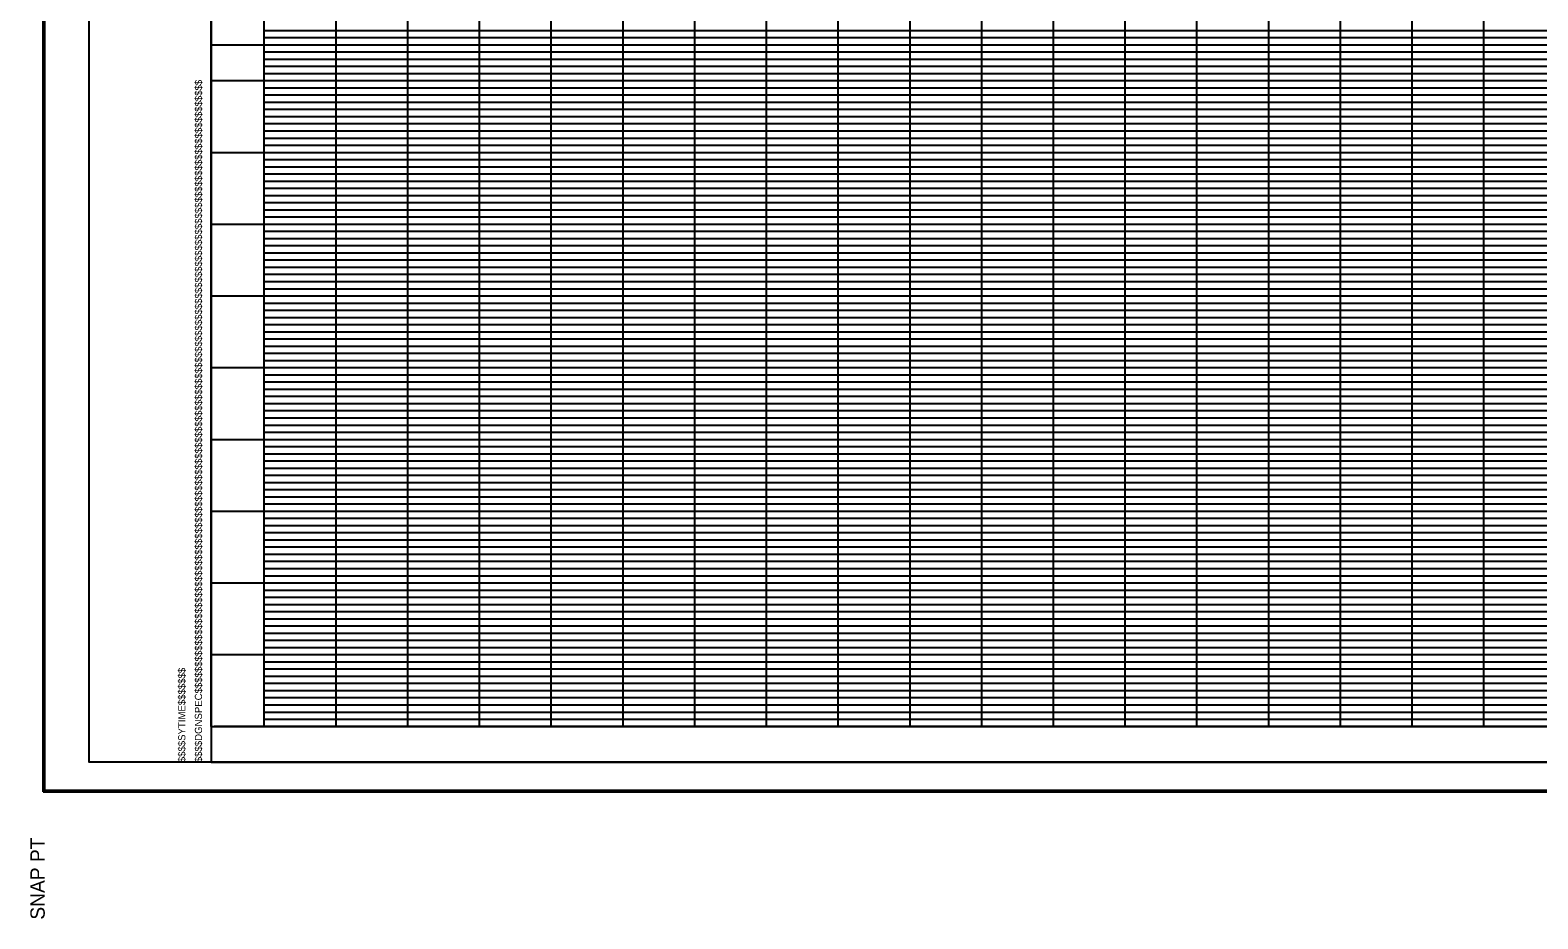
# Model space of a CAD drawing. Extents: x -200 to 1681865, y -325 to 520634.
# Drawn here: x 1680154 to 1681205, y 519391 to 520010 of the extents above; entities that cross this region are included whole.
import ezdxf

# ---------------------------------------------------------------- set-up
doc = ezdxf.new("R2010")
doc.units = 0
for name, color, linetype in [('DESIGN - PROFILE - Proposed Text', 7, 'Continuous'), ('DESIGN - SHEET - Corner Text', 7, 'Continuous'), ('DESIGN - SHEET - Light Grid', 7, 'Continuous'), ('DESIGN - SHEET - Linework', 7, 'Continuous'), ('DESIGN - SHEET - Plot Shape', 7, 'Continuous')]:
    doc.layers.add(name, color=color, linetype=linetype)

msp = doc.modelspace()

# ---------------------------------------------------------------- linework, layer by layer
at = {"layer": 'DESIGN - PROFILE - Proposed Text'}
msp.add_line((1680280, 519499.8), (1680280, 519499.8), dxfattribs=at)
at = {"layer": 'DESIGN - SHEET - Corner Text'}
msp.add_line((1680280, 519999.8), (1681654.2, 519999.8), dxfattribs=at)
at = {"layer": 'DESIGN - SHEET - Light Grid'}
for p, q in [((1680317.1, 520009.8), (1680617.1, 520009.8)), ((1680317.1, 520004.8), (1680617.1, 520004.8)), ((1680617.1, 520009.8), (1680967.1, 520009.8)), ((1680617.1, 520004.8), (1680967.1, 520004.8)), ((1680967.1, 520009.8), (1681317.1, 520009.8)), ((1680967.1, 520004.8), (1681317.1, 520004.8)), ((1680317.1, 519999.8), (1680617.1, 519999.8)), ((1680317.1, 519994.8), (1680617.1, 519994.8)), ((1680617.1, 519999.8), (1680967.1, 519999.8)), ((1680617.1, 519994.8), (1680967.1, 519994.8)), ((1680967.1, 519999.8), (1681317.1, 519999.8)), ((1680967.1, 519994.8), (1681317.1, 519994.8)), ((1680317.1, 519989.8), (1680617.1, 519989.8)), ((1680317.1, 519984.8), (1680617.1, 519984.8)), ((1680617.1, 519989.8), (1680967.1, 519989.8)), ((1680617.1, 519984.8), (1680967.1, 519984.8)), ((1680967.1, 519989.8), (1681317.1, 519989.8)), ((1680967.1, 519984.8), (1681317.1, 519984.8)), ((1680317.1, 519979.8), (1680617.1, 519979.8)), ((1680617.1, 519979.8), (1680967.1, 519979.8)), ((1680967.1, 519979.8), (1681317.1, 519979.8)), ((1680317.1, 519969.8), (1680617.1, 519969.8)), ((1680317.1, 519964.8), (1680617.1, 519964.8)), ((1680317.1, 519959.8), (1680617.1, 519959.8)), ((1680617.1, 519969.8), (1680967.1, 519969.8)), ((1680617.1, 519964.8), (1680967.1, 519964.8)), ((1680617.1, 519959.8), (1680967.1, 519959.8)), ((1680967.1, 519969.8), (1681317.1, 519969.8)), ((1680967.1, 519964.8), (1681317.1, 519964.8)), ((1680967.1, 519959.8), (1681317.1, 519959.8)), ((1680317.1, 519954.8), (1680617.1, 519954.8)), ((1680317.1, 519949.8), (1680617.1, 519949.8)), ((1680617.1, 519954.8), (1680967.1, 519954.8)), ((1680617.1, 519949.8), (1680967.1, 519949.8)), ((1680967.1, 519954.8), (1681317.1, 519954.8)), ((1680967.1, 519949.8), (1681317.1, 519949.8)), ((1680317.1, 519944.8), (1680617.1, 519944.8)), ((1680317.1, 519939.8), (1680617.1, 519939.8)), ((1680617.1, 519944.8), (1680967.1, 519944.8)), ((1680617.1, 519939.8), (1680967.1, 519939.8)), ((1680967.1, 519944.8), (1681317.1, 519944.8)), ((1680967.1, 519939.8), (1681317.1, 519939.8)), ((1680317.1, 519934.8), (1680617.1, 519934.8)), ((1680317.1, 519929.8), (1680617.1, 519929.8)), ((1680617.1, 519934.8), (1680967.1, 519934.8)), ((1680617.1, 519929.8), (1680967.1, 519929.8)), ((1680967.1, 519934.8), (1681317.1, 519934.8)), ((1680967.1, 519929.8), (1681317.1, 519929.8)), ((1680317.1, 519919.8), (1680617.1, 519919.8)), ((1680617.1, 519919.8), (1680967.1, 519919.8)), ((1680967.1, 519919.8), (1681317.1, 519919.8)), ((1680317.1, 519914.8), (1680617.1, 519914.8)), ((1680317.1, 519909.8), (1680617.1, 519909.8)), ((1680617.1, 519914.8), (1680967.1, 519914.8)), ((1680617.1, 519909.8), (1680967.1, 519909.8)), ((1680967.1, 519914.8), (1681317.1, 519914.8)), ((1680967.1, 519909.8), (1681317.1, 519909.8)), ((1680317.1, 519904.8), (1680617.1, 519904.8)), ((1680317.1, 519899.8), (1680617.1, 519899.8)), ((1680617.1, 519904.8), (1680967.1, 519904.8)), ((1680617.1, 519899.8), (1680967.1, 519899.8)), ((1680967.1, 519904.8), (1681317.1, 519904.8)), ((1680967.1, 519899.8), (1681317.1, 519899.8)), ((1680317.1, 519894.8), (1680617.1, 519894.8)), ((1680317.1, 519889.8), (1680617.1, 519889.8)), ((1680617.1, 519894.8), (1680967.1, 519894.8)), ((1680617.1, 519889.8), (1680967.1, 519889.8)), ((1680967.1, 519894.8), (1681317.1, 519894.8)), ((1680967.1, 519889.8), (1681317.1, 519889.8)), ((1680317.1, 519884.8), (1680617.1, 519884.8)), ((1680317.1, 519879.8), (1680617.1, 519879.8)), ((1680617.1, 519884.8), (1680967.1, 519884.8)), ((1680617.1, 519879.8), (1680967.1, 519879.8)), ((1680967.1, 519884.8), (1681317.1, 519884.8)), ((1680967.1, 519879.8), (1681317.1, 519879.8)), ((1680317.1, 519869.8), (1680617.1, 519869.8)), ((1680617.1, 519869.8), (1680967.1, 519869.8)), ((1680967.1, 519869.8), (1681317.1, 519869.8)), ((1680317.1, 519864.8), (1680617.1, 519864.8)), ((1680317.1, 519859.8), (1680617.1, 519859.8)), ((1680317.1, 519854.8), (1680617.1, 519854.8)), ((1680617.1, 519864.8), (1680967.1, 519864.8)), ((1680617.1, 519859.8), (1680967.1, 519859.8)), ((1680617.1, 519854.8), (1680967.1, 519854.8)), ((1680967.1, 519864.8), (1681317.1, 519864.8)), ((1680967.1, 519859.8), (1681317.1, 519859.8)), ((1680967.1, 519854.8), (1681317.1, 519854.8)), ((1680317.1, 519849.8), (1680617.1, 519849.8)), ((1680317.1, 519844.8), (1680617.1, 519844.8)), ((1680617.1, 519849.8), (1680967.1, 519849.8)), ((1680617.1, 519844.8), (1680967.1, 519844.8)), ((1680967.1, 519849.8), (1681317.1, 519849.8)), ((1680967.1, 519844.8), (1681317.1, 519844.8)), ((1680317.1, 519839.8), (1680617.1, 519839.8)), ((1680317.1, 519834.8), (1680617.1, 519834.8)), ((1680617.1, 519839.8), (1680967.1, 519839.8)), ((1680617.1, 519834.8), (1680967.1, 519834.8)), ((1680967.1, 519839.8), (1681317.1, 519839.8)), ((1680967.1, 519834.8), (1681317.1, 519834.8)), ((1680317.1, 519829.8), (1680617.1, 519829.8)), ((1680617.1, 519829.8), (1680967.1, 519829.8)), ((1680967.1, 519829.8), (1681317.1, 519829.8)), ((1680317.1, 519819.8), (1680617.1, 519819.8)), ((1680317.1, 519814.8), (1680617.1, 519814.8)), ((1680617.1, 519819.8), (1680967.1, 519819.8)), ((1680617.1, 519814.8), (1680967.1, 519814.8)), ((1680967.1, 519819.8), (1681317.1, 519819.8)), ((1680967.1, 519814.8), (1681317.1, 519814.8)), ((1680317.1, 519809.8), (1680617.1, 519809.8)), ((1680317.1, 519804.8), (1680617.1, 519804.8)), ((1680617.1, 519809.8), (1680967.1, 519809.8)), ((1680617.1, 519804.8), (1680967.1, 519804.8)), ((1680967.1, 519809.8), (1681317.1, 519809.8)), ((1680967.1, 519804.8), (1681317.1, 519804.8)), ((1680317.1, 519799.8), (1680617.1, 519799.8)), ((1680317.1, 519794.8), (1680617.1, 519794.8)), ((1680617.1, 519799.8), (1680967.1, 519799.8)), ((1680617.1, 519794.8), (1680967.1, 519794.8)), ((1680967.1, 519799.8), (1681317.1, 519799.8)), ((1680967.1, 519794.8), (1681317.1, 519794.8)), ((1680317.1, 519789.8), (1680617.1, 519789.8)), ((1680317.1, 519784.8), (1680617.1, 519784.8)), ((1680617.1, 519789.8), (1680967.1, 519789.8)), ((1680617.1, 519784.8), (1680967.1, 519784.8)), ((1680967.1, 519789.8), (1681317.1, 519789.8)), ((1680967.1, 519784.8), (1681317.1, 519784.8)), ((1680317.1, 519779.8), (1680617.1, 519779.8)), ((1680617.1, 519779.8), (1680967.1, 519779.8)), ((1680967.1, 519779.8), (1681317.1, 519779.8)), ((1680317.1, 519769.8), (1680617.1, 519769.8)), ((1680317.1, 519764.8), (1680617.1, 519764.8)), ((1680317.1, 519759.8), (1680617.1, 519759.8)), ((1680617.1, 519769.8), (1680967.1, 519769.8)), ((1680617.1, 519764.8), (1680967.1, 519764.8)), ((1680617.1, 519759.8), (1680967.1, 519759.8)), ((1680967.1, 519769.8), (1681317.1, 519769.8)), ((1680967.1, 519764.8), (1681317.1, 519764.8)), ((1680967.1, 519759.8), (1681317.1, 519759.8)), ((1680317.1, 519754.8), (1680617.1, 519754.8)), ((1680317.1, 519749.8), (1680617.1, 519749.8)), ((1680617.1, 519754.8), (1680967.1, 519754.8)), ((1680617.1, 519749.8), (1680967.1, 519749.8)), ((1680967.1, 519754.8), (1681317.1, 519754.8)), ((1680967.1, 519749.8), (1681317.1, 519749.8)), ((1680317.1, 519744.8), (1680617.1, 519744.8)), ((1680317.1, 519739.8), (1680617.1, 519739.8)), ((1680617.1, 519744.8), (1680967.1, 519744.8)), ((1680617.1, 519739.8), (1680967.1, 519739.8)), ((1680967.1, 519744.8), (1681317.1, 519744.8)), ((1680967.1, 519739.8), (1681317.1, 519739.8)), ((1680317.1, 519734.8), (1680617.1, 519734.8)), ((1680317.1, 519729.8), (1680617.1, 519729.8)), ((1680617.1, 519734.8), (1680967.1, 519734.8)), ((1680617.1, 519729.8), (1680967.1, 519729.8)), ((1680967.1, 519734.8), (1681317.1, 519734.8)), ((1680967.1, 519729.8), (1681317.1, 519729.8)), ((1680317.1, 519719.8), (1680617.1, 519719.8)), ((1680617.1, 519719.8), (1680967.1, 519719.8)), ((1680967.1, 519719.8), (1681317.1, 519719.8)), ((1680317.1, 519714.8), (1680617.1, 519714.8)), ((1680317.1, 519709.8), (1680617.1, 519709.8)), ((1680617.1, 519714.8), (1680967.1, 519714.8)), ((1680617.1, 519709.8), (1680967.1, 519709.8)), ((1680967.1, 519714.8), (1681317.1, 519714.8)), ((1680967.1, 519709.8), (1681317.1, 519709.8)), ((1680317.1, 519704.8), (1680617.1, 519704.8)), ((1680317.1, 519699.8), (1680617.1, 519699.8)), ((1680617.1, 519704.8), (1680967.1, 519704.8)), ((1680617.1, 519699.8), (1680967.1, 519699.8)), ((1680967.1, 519704.8), (1681317.1, 519704.8)), ((1680967.1, 519699.8), (1681317.1, 519699.8)), ((1680317.1, 519694.8), (1680617.1, 519694.8)), ((1680317.1, 519689.8), (1680617.1, 519689.8)), ((1680617.1, 519694.8), (1680967.1, 519694.8)), ((1680617.1, 519689.8), (1680967.1, 519689.8)), ((1680967.1, 519694.8), (1681317.1, 519694.8)), ((1680967.1, 519689.8), (1681317.1, 519689.8)), ((1680317.1, 519684.8), (1680617.1, 519684.8)), ((1680317.1, 519679.8), (1680617.1, 519679.8)), ((1680617.1, 519684.8), (1680967.1, 519684.8)), ((1680617.1, 519679.8), (1680967.1, 519679.8)), ((1680967.1, 519684.8), (1681317.1, 519684.8)), ((1680967.1, 519679.8), (1681317.1, 519679.8)), ((1680317.1, 519669.8), (1680617.1, 519669.8)), ((1680617.1, 519669.8), (1680967.1, 519669.8)), ((1680967.1, 519669.8), (1681317.1, 519669.8)), ((1680317.1, 519664.8), (1680617.1, 519664.8)), ((1680317.1, 519659.8), (1680617.1, 519659.8)), ((1680317.1, 519654.8), (1680617.1, 519654.8)), ((1680617.1, 519664.8), (1680967.1, 519664.8)), ((1680617.1, 519659.8), (1680967.1, 519659.8)), ((1680617.1, 519654.8), (1680967.1, 519654.8)), ((1680967.1, 519664.8), (1681317.1, 519664.8)), ((1680967.1, 519659.8), (1681317.1, 519659.8)), ((1680967.1, 519654.8), (1681317.1, 519654.8)), ((1680317.1, 519649.8), (1680617.1, 519649.8)), ((1680317.1, 519644.8), (1680617.1, 519644.8)), ((1680617.1, 519649.8), (1680967.1, 519649.8)), ((1680617.1, 519644.8), (1680967.1, 519644.8)), ((1680967.1, 519649.8), (1681317.1, 519649.8)), ((1680967.1, 519644.8), (1681317.1, 519644.8)), ((1680317.1, 519639.8), (1680617.1, 519639.8)), ((1680317.1, 519634.8), (1680617.1, 519634.8)), ((1680617.1, 519639.8), (1680967.1, 519639.8)), ((1680617.1, 519634.8), (1680967.1, 519634.8)), ((1680967.1, 519639.8), (1681317.1, 519639.8)), ((1680967.1, 519634.8), (1681317.1, 519634.8)), ((1680317.1, 519629.8), (1680617.1, 519629.8)), ((1680617.1, 519629.8), (1680967.1, 519629.8)), ((1680967.1, 519629.8), (1681317.1, 519629.8)), ((1680317.1, 519619.8), (1680617.1, 519619.8)), ((1680317.1, 519614.8), (1680617.1, 519614.8)), ((1680617.1, 519619.8), (1680967.1, 519619.8)), ((1680617.1, 519614.8), (1680967.1, 519614.8)), ((1680967.1, 519619.8), (1681317.1, 519619.8)), ((1680967.1, 519614.8), (1681317.1, 519614.8)), ((1680317.1, 519609.8), (1680617.1, 519609.8)), ((1680317.1, 519604.8), (1680617.1, 519604.8)), ((1680617.1, 519609.8), (1680967.1, 519609.8)), ((1680617.1, 519604.8), (1680967.1, 519604.8)), ((1680967.1, 519609.8), (1681317.1, 519609.8)), ((1680967.1, 519604.8), (1681317.1, 519604.8)), ((1680317.1, 519599.8), (1680617.1, 519599.8)), ((1680317.1, 519594.8), (1680617.1, 519594.8)), ((1680617.1, 519599.8), (1680967.1, 519599.8)), ((1680617.1, 519594.8), (1680967.1, 519594.8)), ((1680967.1, 519599.8), (1681317.1, 519599.8)), ((1680967.1, 519594.8), (1681317.1, 519594.8)), ((1680317.1, 519589.8), (1680617.1, 519589.8)), ((1680317.1, 519584.8), (1680617.1, 519584.8)), ((1680617.1, 519589.8), (1680967.1, 519589.8)), ((1680617.1, 519584.8), (1680967.1, 519584.8)), ((1680967.1, 519589.8), (1681317.1, 519589.8)), ((1680967.1, 519584.8), (1681317.1, 519584.8)), ((1680317.1, 519579.8), (1680617.1, 519579.8)), ((1680617.1, 519579.8), (1680967.1, 519579.8)), ((1680967.1, 519579.8), (1681317.1, 519579.8)), ((1680317.1, 519569.8), (1680617.1, 519569.8)), ((1680317.1, 519564.8), (1680617.1, 519564.8)), ((1680617.1, 519569.8), (1680967.1, 519569.8)), ((1680617.1, 519564.8), (1680967.1, 519564.8)), ((1680967.1, 519569.8), (1681317.1, 519569.8)), ((1680967.1, 519564.8), (1681317.1, 519564.8)), ((1680317.1, 519559.8), (1680617.1, 519559.8)), ((1680317.1, 519554.8), (1680617.1, 519554.8)), ((1680317.1, 519549.8), (1680617.1, 519549.8)), ((1680617.1, 519559.8), (1680967.1, 519559.8)), ((1680617.1, 519554.8), (1680967.1, 519554.8)), ((1680617.1, 519549.8), (1680967.1, 519549.8)), ((1680967.1, 519559.8), (1681317.1, 519559.8)), ((1680967.1, 519554.8), (1681317.1, 519554.8)), ((1680967.1, 519549.8), (1681317.1, 519549.8)), ((1680317.1, 519544.8), (1680617.1, 519544.8)), ((1680317.1, 519539.8), (1680617.1, 519539.8)), ((1680617.1, 519544.8), (1680967.1, 519544.8)), ((1680617.1, 519539.8), (1680967.1, 519539.8)), ((1680967.1, 519544.8), (1681317.1, 519544.8)), ((1680967.1, 519539.8), (1681317.1, 519539.8)), ((1680317.1, 519534.8), (1680617.1, 519534.8)), ((1680317.1, 519529.8), (1680617.1, 519529.8)), ((1680617.1, 519534.8), (1680967.1, 519534.8)), ((1680617.1, 519529.8), (1680967.1, 519529.8)), ((1680967.1, 519534.8), (1681317.1, 519534.8)), ((1680967.1, 519529.8), (1681317.1, 519529.8))]:
    msp.add_line(p, q, dxfattribs=at)
at = {"layer": 'DESIGN - SHEET - Linework'}
for p, q in [((1680163.1, 519479.1), (1680163.1, 520570.5)), ((1680317.1, 519524.8), (1680317.1, 520524.8)), ((1680367.1, 519524.8), (1680367.1, 520524.8)), ((1680417.1, 519524.8), (1680417.1, 520524.8)), ((1680467.1, 519524.8), (1680467.1, 520524.8)), ((1680517.1, 519524.8), (1680517.1, 520524.8)), ((1680567.1, 519524.8), (1680567.1, 520524.8)), ((1680617.1, 519524.8), (1680617.1, 520524.8)), ((1680667.1, 519524.8), (1680667.1, 520524.8)), ((1680717.1, 519524.8), (1680717.1, 520524.8)), ((1680767.1, 519524.8), (1680767.1, 520524.8)), ((1680817.1, 519524.8), (1680817.1, 520524.8)), ((1680867.1, 519524.8), (1680867.1, 520524.8)), ((1680917.1, 519524.8), (1680917.1, 520524.8)), ((1680967.1, 519524.8), (1680967.1, 520524.8)), ((1681017.1, 519524.8), (1681017.1, 520524.8)), ((1681067.1, 519524.8), (1681067.1, 520524.8)), ((1681117.1, 519524.8), (1681117.1, 520524.8)), ((1681167.1, 519524.8), (1681167.1, 520524.8)), ((1680280, 519974.8), (1681654.2, 519974.8)), ((1680280, 519924.8), (1681654.2, 519924.8)), ((1680280, 519874.8), (1681654.2, 519874.8)), ((1680280, 519824.8), (1681654.2, 519824.8)), ((1680280, 519774.8), (1681654.2, 519774.8)), ((1680280, 519724.8), (1681654.2, 519724.8)), ((1680280, 519674.8), (1681654.2, 519674.8)), ((1680280, 519624.8), (1681654.2, 519624.8)), ((1680280, 519574.8), (1681654.2, 519574.8)), ((1680280, 519524.8), (1681654.2, 519524.8)), ((1680163.1, 519479.1), (1681865.1, 519479.1))]:
    msp.add_line(p, q, dxfattribs=at)
for points in [[(1680280, 520549.8), (1680280, 519499.8), (1681854.2, 519499.8), (1681854.2, 520549.8), (1680280, 520549.8)], [(1680280, 519524.8), (1680280, 520524.8), (1681654.2, 520524.8), (1681654.2, 519524.8), (1680282.1, 519524.8)]]:
    msp.add_lwpolyline(points, dxfattribs=at)
at = {"layer": 'DESIGN - SHEET - Plot Shape'}
for points in [[(1680164.1, 520569.5), (1681864.1, 520569.5), (1681864.1, 519480.1), (1680164.1, 519480.1)], [(1680195, 520549.8), (1681854.2, 520549.8), (1681854.2, 519499.8), (1680195, 519499.8)]]:
    msp.add_lwpolyline(points, close=True, dxfattribs=at)

# ---------------------------------------------------------------- texts
at = {"layer": 'DESIGN - SHEET - Corner Text'}
for s, height, p in [('$$$$DGNSPEC$$$$$$$$$$$$$$$$$$$$$$$$$$$$$$$$$$$$$$$$$$$$$$$$$$$$$$$$$$$$$$$$$$$$$$$$$$$$$$$$$$$$$$$$$$$$$$$$$$$$$$$$$$$$$$$$$$$', 5.0001, (1680273.7, 519499.8)), ('$$$$SYTIME$$$$$$$', 5, (1680262.1, 519499.8)), ('SNAP PT  ', 10, (1680164.1, 519390.1))]:
    msp.add_text(s, height=height, rotation=90, dxfattribs=at).set_placement(p)

doc.saveas('drawing.dxf')
